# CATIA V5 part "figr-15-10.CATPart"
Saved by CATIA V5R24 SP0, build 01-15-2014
Part number: Part1
Bounding box of the stored display mesh (mm): x -50 to 50, y -32.5 to 33.5, z -52 to 1
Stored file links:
  D:\KAVITA\CATIA V5-6R2014 Project_ Kavita\CATIA V5-6R2014_partfiles\Partfiles\c15_catia_v5-6r2014_prt\figr-15-10.CATPart
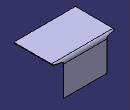
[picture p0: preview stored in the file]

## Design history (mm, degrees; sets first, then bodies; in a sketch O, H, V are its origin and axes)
SheetMetalParameters1: Thickness 1, BendRadius 4, KFactor 0.475772 {= log(min(100,max(20*SheetMetalParameters1.BendRadius,SheetMetalParameters1.Thickness)/SheetMetalParameters1.Thickness))/log(100)/2}, ReliefRadialLength 4, ReliefAxialLength 4, MinimumBendRadius 0
Body1 (main body)
  Sketch1 on xy-plane, origin (0, 0, 0), H (1, 0, 0), V (0, 1, 0)
    line L1 (-50, 32.5) -> (50, 32.5)
    line L2 (50, 32.5) -> (50, -32.5)
    line L3 (50, -32.5) -> (-50, -32.5)
    line L4 (-50, -32.5) -> (-50, 32.5)
    length L1 = 100
    length L2 = 65
    horizontal: L1 H, L3 H
    vertical: L2 V, L4 V
    symmetry: L4 L2 V, L1 L3 H
  Wall1: Thickness 1, Profile Sketch1
  d_NewWallOnEdge1: NewWallOnEdge_Edge edge [face of Wall1 | face of Wall1], NewWallOnEdge_Length 53, NewWallOnEdge_HeightLimitOffset 0, NewWallOnEdge_WidthOffset1 -15, NewWallOnEdge_WidthOffset2 -15, NewWallOnEdge_Angle 90, NewWallOnEdge_BendRadiusValue 4 {= SheetMetalParameters1.BendRadius}, NewWallOnEdge_BendTable SheetMetalParameters1, KFacteur 0.475772 {= log(min(100,max(20*d_NewWallOnEdge1.Radius,SheetMetalParameters1.Thickness)/SheetMetalParameters1.Thickness))/log(100)/2}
